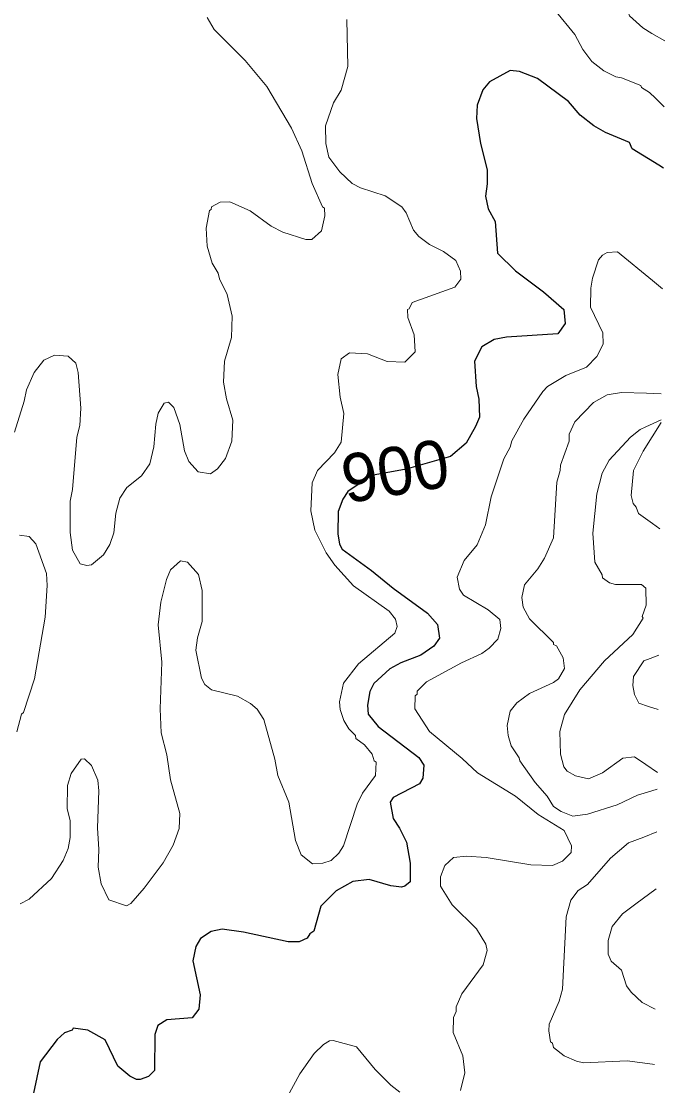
# Model space of a CAD drawing. Extents: x 598.3 to 623.2, y 6902.2 to 6930.1.
# Drawn here: x 621.986 to 623.056, y 6914.688 to 6916.455 of the extents above; entities that cross this region are included whole.
import ezdxf
from ezdxf.enums import TextEntityAlignment as Align

# ---------------------------------------------------------------- set-up
doc = ezdxf.new("R2010")
doc.units = 0
doc.header["$LTSCALE"] = 0.032
doc.layers.add('1', color=7, linetype='Continuous', lineweight=25)
doc.layers.add('2', color=7, linetype='Continuous', lineweight=13)
doc.layers.add('61', color=7, linetype='Continuous')

msp = doc.modelspace()

# ---------------------------------------------------------------- linework, layer by layer
at = {"layer": '1'}
for points in [[(623.0527, 6916.2114), (623.0446, 6916.2164), (623.0006, 6916.2435), (622.9958, 6916.2538), (622.9563, 6916.2704), (622.9368, 6916.2814), (622.9142, 6916.2993), (622.8947, 6916.3219), (622.843, 6916.3604), (622.8132, 6916.3719), (622.7978, 6916.3732), (622.7637, 6916.3547), (622.7526, 6916.3413), (622.743, 6916.316), (622.742, 6916.2939), (622.7484, 6916.2521), (622.7597, 6916.2084), (622.7597, 6916.1854), (622.7566, 6916.1647), (622.7613, 6916.1439), (622.7727, 6916.1226), (622.7767, 6916.0702), (622.8066, 6916.0408), (622.8534, 6916.0062), (622.8871, 6915.9765), (622.8892, 6915.9537), (622.8768, 6915.9364), (622.7918, 6915.9307), (622.7711, 6915.9267), (622.7506, 6915.9149), (622.7388, 6915.8909), (622.7412, 6915.8487), (622.7459, 6915.8279), (622.7468, 6915.798), (622.7403, 6915.7827), (622.7247, 6915.7548), (622.6985, 6915.7329), (622.6253, 6915.7119), (622.5677, 6915.7012), (622.5279, 6915.6744), (622.5198, 6915.662), (622.5121, 6915.6417), (622.5113, 6915.6042), (622.5143, 6915.5874), (622.5187, 6915.5787), (622.5675, 6915.5437), (622.6034, 6915.5142), (622.6607, 6915.4727), (622.6772, 6915.454), (622.6803, 6915.4314), (622.6709, 6915.4178), (622.6494, 6915.4028), (622.6163, 6915.3903), (622.5981, 6915.3805), (622.5712, 6915.356), (622.5647, 6915.3426), (622.5607, 6915.3199), (622.562, 6915.3053), (622.5784, 6915.2847), (622.6461, 6915.2332), (622.6545, 6915.2206), (622.653, 6915.1988), (622.6473, 6915.1895), (622.6034, 6915.1669), (622.5987, 6915.159), (622.6035, 6915.1316), (622.6142, 6915.116), (622.6254, 6915.0926), (622.6318, 6915.0576), (622.6317, 6915.0266), (622.6231, 6915.0194), (622.6175, 6915.0177), (622.5998, 6915.02), (622.5638, 6915.0305), (622.5366, 6915.0274), (622.5086, 6915.0117), (622.4831, 6914.9861), (622.4715, 6914.945), (622.4649, 6914.9405), (622.4604, 6914.9331), (622.4473, 6914.927), (622.4292, 6914.927), (622.355, 6914.9431), (622.3197, 6914.948), (622.301, 6914.9443), (622.2834, 6914.9328), (622.2758, 6914.9192), (622.2709, 6914.8957), (622.2829, 6914.839), (622.2805, 6914.8152), (622.2697, 6914.8007), (622.2277, 6914.7975), (622.2126, 6914.7884), (622.2076, 6914.7733), (622.2068, 6914.7136), (622.1973, 6914.7037), (622.1834, 6914.6987), (622.1769, 6914.6987), (622.1662, 6914.704), (622.1462, 6914.7206)], [(622.1462, 6914.7206), (622.1249, 6914.7644), (622.0963, 6914.7803), (622.072, 6914.7837), (622.0705, 6914.7804), (622.0577, 6914.7762), (622.0455, 6914.7648), (622.0172, 6914.7279), (622.0063, 6914.6759)]]:
    msp.add_lwpolyline(points, dxfattribs=at)
at = {"layer": '2'}
for points in [[(623.0562, 6916.5526), (623.0407, 6916.5663), (623.0177, 6916.5866), (622.9985, 6916.609), (622.9834, 6916.6222), (622.9639, 6916.6251), (622.9541, 6916.6131), (622.9517, 6916.6014), (622.9599, 6916.5818), (622.9796, 6916.5495), (622.9801, 6916.5443), (622.9844, 6916.5414), (622.9849, 6916.5346), (622.988, 6916.5319), (622.9889, 6916.485), (622.9962, 6916.4644), (623.0179, 6916.4441), (623.0334, 6916.4351), (623.0549, 6916.4226)], [(622.2948, 6916.4613), (622.3061, 6916.4415), (622.3578, 6916.3902), (622.3937, 6916.3468), (622.4346, 6916.2775), (622.4518, 6916.2401), (622.4691, 6916.186), (622.4861, 6916.1473), (622.4893, 6916.145), (622.4901, 6916.1323), (622.4846, 6916.1074), (622.4684, 6916.0927), (622.4586, 6916.0927), (622.4204, 6916.1053), (622.4009, 6916.1151), (622.3661, 6916.1405), (622.3323, 6916.1557), (622.3161, 6916.1549), (622.3019, 6916.147), (622.3014, 6916.1429), (622.2984, 6916.141), (622.2927, 6916.1118), (622.2943, 6916.0821), (622.3029, 6916.0536), (622.3128, 6916.0371), (622.3149, 6916.0279), (622.3278, 6916.0019), (622.3363, 6915.9655), (622.3348, 6915.9305), (622.3234, 6915.8909), (622.3219, 6915.8564), (622.3268, 6915.8285), (622.3371, 6915.7929), (622.3355, 6915.7583), (622.325, 6915.7292), (622.3115, 6915.7123), (622.3001, 6915.7042), (622.2794, 6915.7074), (622.2642, 6915.7246), (622.2571, 6915.7419), (622.249, 6915.7856), (622.2392, 6915.8139), (622.2302, 6915.8229), (622.2233, 6915.8214), (622.2131, 6915.8044), (622.2091, 6915.7865), (622.206, 6915.7486), (622.1991, 6915.7204), (622.1857, 6915.7008), (622.1613, 6915.6811), (622.1497, 6915.6637), (622.143, 6915.6387), (622.1396, 6915.6061), (622.1331, 6915.5865), (622.1222, 6915.5693), (622.1026, 6915.5529), (622.0944, 6915.552), (622.0835, 6915.5547), (622.0708, 6915.5773), (622.0668, 6915.6065), (622.0669, 6915.6585), (622.0709, 6915.678), (622.0782, 6915.7648), (622.083, 6915.784), (622.0846, 6915.8128), (622.0804, 6915.8722), (622.0764, 6915.8877), (622.0639, 6915.8992), (622.041, 6915.9007), (622.0232, 6915.8926), (622.0071, 6915.8719), (621.9943, 6915.8435), (621.9907, 6915.8248), (621.9746, 6915.7732)], [(622.5266, 6916.4583), (622.5283, 6916.38), (622.517, 6916.3406), (622.5046, 6916.3199), (622.491, 6916.2815), (622.4918, 6916.2521), (622.4967, 6916.2298), (622.5151, 6916.2051), (622.5355, 6916.1858), (622.5493, 6916.1785), (622.59, 6916.1653), (622.6179, 6916.1469), (622.6253, 6916.1371), (622.6374, 6916.1082), (622.6461, 6916.0978), (622.6637, 6916.0846), (622.6871, 6916.0731), (622.7077, 6916.058), (622.7151, 6916.0406), (622.7159, 6916.0273), (622.706, 6916.014), (622.6351, 6915.9882), (622.6302, 6915.9779), (622.6272, 6915.9766), (622.628, 6915.9634), (622.6384, 6915.9346), (622.64, 6915.9062), (622.6227, 6915.8894), (622.5934, 6915.8903), (622.5606, 6915.9032), (622.5311, 6915.9047), (622.5169, 6915.8948), (622.5113, 6915.8691), (622.5153, 6915.8312), (622.5217, 6915.8039), (622.5169, 6915.7567), (622.5063, 6915.7386), (622.478, 6915.7097), (622.4692, 6915.689), (622.4668, 6915.6425), (622.4734, 6915.6105), (622.4923, 6915.5728), (622.5067, 6915.5524), (622.5378, 6915.5181), (622.5969, 6915.4759), (622.6073, 6915.4627), (622.6099, 6915.4506), (622.6061, 6915.4396), (622.5461, 6915.3885), (622.521, 6915.3567), (622.5145, 6915.3256), (622.5153, 6915.3129), (622.5215, 6915.2943), (622.5297, 6915.2807), (622.5409, 6915.2697), (622.5413, 6915.2648), (622.5558, 6915.254), (622.5685, 6915.2389)], [(623.0538, 6916.3132), (623.0391, 6916.3275), (623.0295, 6916.3369), (623.0158, 6916.3451), (623.0151, 6916.3485), (622.983, 6916.3614), (622.9734, 6916.3631), (622.9533, 6916.3727), (622.9336, 6916.3884), (622.9184, 6916.4083), (622.9054, 6916.4334), (622.8728, 6916.4731)], [(622.9317, 6916.0119), (622.9346, 6916.0289), (622.9444, 6916.0594), (622.9511, 6916.067), (622.9591, 6916.0716), (622.9759, 6916.0723), (623.0342, 6916.0247), (623.0507, 6916.0113)], [(622.7152, 6914.6801), (622.7225, 6914.7095), (622.7194, 6914.7378), (622.7032, 6914.7767), (622.7039, 6914.8013), (622.7079, 6914.8113), (622.7081, 6914.8193), (622.7178, 6914.8406), (622.7531, 6914.8887), (622.7598, 6914.913), (622.7572, 6914.9232), (622.7421, 6914.9486), (622.7016, 6914.9883), (622.6821, 6915.0195), (622.6821, 6915.0349), (622.6893, 6915.054), (622.7038, 6915.0672), (622.7252, 6915.0694), (622.7579, 6915.0671), (622.832, 6915.0547), (622.868, 6915.054), (622.8848, 6915.0608), (622.8989, 6915.0754), (622.8997, 6915.0867), (622.8873, 6915.1118), (622.8442, 6915.1386), (622.8067, 6915.169), (622.7434, 6915.2076), (622.7181, 6915.2317), (622.6638, 6915.2762), (622.6392, 6915.314), (622.64, 6915.3354), (622.6431, 6915.3385), (622.6434, 6915.3431), (622.6586, 6915.3586), (622.7169, 6915.3905), (622.7505, 6915.4056), (622.7632, 6915.4144), (622.7774, 6915.4295), (622.7824, 6915.4473), (622.7807, 6915.462), (622.7614, 6915.4782), (622.7202, 6915.5024), (622.7135, 6915.5126), (622.7097, 6915.5322), (622.7215, 6915.5603), (622.7429, 6915.5859), (622.7566, 6915.6194), (622.7662, 6915.666), (622.7872, 6915.729), (622.7977, 6915.7481), (622.8006, 6915.7589), (622.8203, 6915.7945), (622.8522, 6915.8409), (622.8601, 6915.8489), (622.8904, 6915.8674), (622.9246, 6915.8809), (622.942, 6915.8985), (622.9525, 6915.9192), (622.9516, 6915.938), (622.9314, 6915.9804), (622.9317, 6916.0119)], [(623.0489, 6915.8368), (623.0245, 6915.8377), (622.9827, 6915.8392), (622.9592, 6915.8353), (622.9362, 6915.8222), (622.9052, 6915.7902), (622.8959, 6915.7698), (622.8957, 6915.7584), (622.8813, 6915.7183), (622.8811, 6915.7097), (622.8755, 6915.6901), (622.8698, 6915.598), (622.8551, 6915.5638), (622.8437, 6915.5462), (622.8214, 6915.5196), (622.8173, 6915.4985), (622.8194, 6915.4824), (622.8297, 6915.4632), (622.8697, 6915.424), (622.87, 6915.4208), (622.8749, 6915.4186), (622.886, 6915.3987), (622.8883, 6915.381), (622.8781, 6915.3635), (622.8699, 6915.3574), (622.8299, 6915.3392), (622.8088, 6915.324), (622.7977, 6915.3102), (622.793, 6915.2863), (622.7945, 6915.2697), (622.7994, 6915.2522), (622.8128, 6915.2325), (622.8136, 6915.2275), (622.8392, 6915.1915), (622.8593, 6915.169), (622.87, 6915.152), (622.8826, 6915.1432), (622.902, 6915.1359), (622.9265, 6915.139), (622.9754, 6915.1545), (623.0091, 6915.1706), (623.0261, 6915.1756), (623.0422, 6915.1803)], [(623.0484, 6915.7938), (623.0229, 6915.7819), (623.0137, 6915.7776), (622.9978, 6915.7648), (622.9622, 6915.7265), (622.9507, 6915.7049), (622.9418, 6915.6707), (622.9354, 6915.6055), (622.9386, 6915.5574), (622.9508, 6915.5363), (622.9511, 6915.5315), (622.9629, 6915.5229), (622.9728, 6915.5201), (623.0158, 6915.5205), (623.0234, 6915.514), (623.0238, 6915.4862), (623.0173, 6915.4672), (623.0185, 6915.4645), (623.0016, 6915.4374), (622.9544, 6915.3936), (622.9134, 6915.3453), (622.8883, 6915.3046), (622.8804, 6915.2761), (622.8816, 6915.2385), (622.887, 6915.2174), (622.8925, 6915.2104), (622.9063, 6915.2025), (622.9281, 6915.1976), (622.9511, 6915.2075), (622.985, 6915.2318), (623.0043, 6915.2344), (623.0229, 6915.2217), (623.0425, 6915.2083)], [(623.0484, 6915.7889), (623.0189, 6915.7414), (623.0026, 6915.7097), (622.9986, 6915.6679), (623.0021, 6915.6547), (623.0073, 6915.6489), (623.0112, 6915.6379), (623.0342, 6915.6216), (623.0466, 6915.6128)], [(621.9786, 6915.2756), (621.9859, 6915.305), (621.9892, 6915.3079), (622.0078, 6915.3636), (622.0256, 6915.4659), (622.0287, 6915.5185), (622.0278, 6915.5384), (622.0097, 6915.588), (621.9989, 6915.6002), (621.9826, 6915.602)], [(622.5685, 6915.2389), (622.572, 6915.2276), (622.5751, 6915.2254), (622.5743, 6915.2033), (622.5524, 6915.1737), (622.5435, 6915.1558), (622.521, 6915.0867), (622.513, 6915.0745), (622.5005, 6915.0621), (622.4868, 6915.0579), (622.4695, 6915.0565), (622.4507, 6915.0718), (622.4413, 6915.0956), (622.4304, 6915.1588), (622.4118, 6915.2034), (622.4069, 6915.2303), (622.3889, 6915.296), (622.3774, 6915.3133), (622.3663, 6915.3228), (622.3451, 6915.3349), (622.3016, 6915.3455), (622.2909, 6915.3545), (622.2853, 6915.3649), (622.2756, 6915.4112), (622.2787, 6915.432), (622.2863, 6915.4591), (622.2863, 6915.5101), (622.2803, 6915.5366), (622.2621, 6915.5573), (622.25, 6915.5598), (622.2337, 6915.5448), (622.2272, 6915.5287), (622.2173, 6915.491), (622.2134, 6915.4533), (622.2191, 6915.3913), (622.2166, 6915.3141), (622.2182, 6915.2742), (622.2278, 6915.2376), (622.2336, 6915.1963), (622.2489, 6915.1399), (622.248, 6915.1151), (622.2383, 6915.0878), (622.2216, 6915.0584), (622.19, 6915.0163), (622.1679, 6914.991), (622.1605, 6914.9869), (622.1314, 6914.9969), (622.1183, 6915.0232), (622.1133, 6915.0512), (622.1144, 6915.0806), (622.1121, 6915.1166), (622.1145, 6915.1777), (622.1128, 6915.1955), (622.1024, 6915.22), (622.0908, 6915.231), (622.0853, 6915.2304), (622.0686, 6915.2065), (622.0627, 6915.1866), (622.062, 6915.148), (622.0669, 6915.1283), (622.0668, 6915.1005), (622.0637, 6915.0822), (622.0553, 6915.0619), (622.036, 6915.0323), (621.9986, 6914.998), (621.984, 6914.9901)], [(623.0445, 6915.4031), (623.0302, 6915.3974), (623.0199, 6915.3933), (623.0026, 6915.3678), (623.0018, 6915.3528), (623.0044, 6915.3375), (623.0113, 6915.3233), (623.0278, 6915.318), (623.0436, 6915.3129)], [(623.0415, 6915.1097), (623.0197, 6915.1011), (622.9945, 6915.0912), (622.9645, 6915.0662), (622.9263, 6915.0223), (622.9105, 6915.0121), (622.8985, 6914.9965), (622.8909, 6914.9685), (622.8845, 6914.8487), (622.8793, 6914.8285), (622.8626, 6914.7905), (622.8618, 6914.7795), (622.865, 6914.7613), (622.868, 6914.7587), (622.8698, 6914.7517), (622.8877, 6914.7379), (622.9081, 6914.7288), (622.9198, 6914.7263), (622.9919, 6914.7294), (623.0342, 6914.7239), (623.0375, 6914.7235)], [(623.0405, 6915.0153), (623.0067, 6914.9902), (622.9846, 6914.9738), (622.9671, 6914.9524), (622.9605, 6914.9296), (622.9606, 6914.9068), (622.9655, 6914.8953), (622.983, 6914.8799), (622.991, 6914.8539), (622.9986, 6914.8436), (623.0173, 6914.8265), (623.0385, 6914.8156)], [(622.4273, 6914.6693), (622.4483, 6914.7079), (622.4723, 6914.7419), (622.4878, 6914.7569), (622.4975, 6914.7626), (622.504, 6914.7634), (622.5424, 6914.7526), (622.5737, 6914.7154), (622.5994, 6914.689), (622.6144, 6914.6776)]]:
    msp.add_lwpolyline(points, dxfattribs=at)

# ---------------------------------------------------------------- texts
at = {"layer": '61'}
msp.add_text('900', height=0.08, rotation=9.462, dxfattribs=at).set_placement((622.6134, 6915.6694), align=Align.CENTER)

doc.saveas('drawing.dxf')
